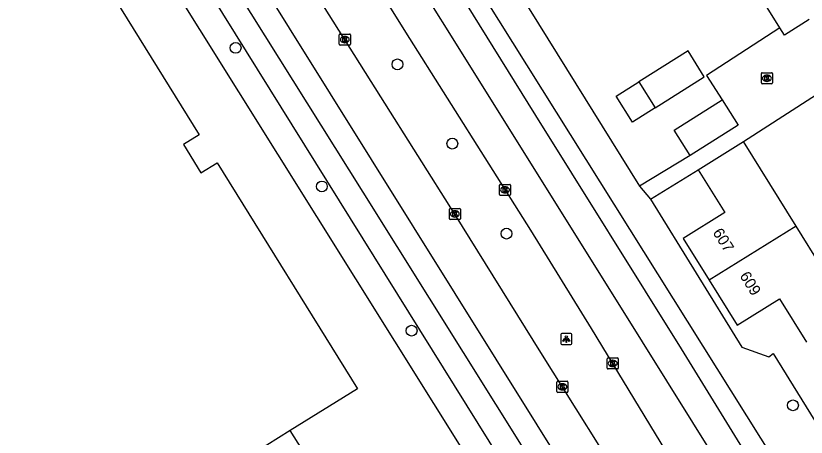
# Model space of a CAD drawing. Extents: x 158461 to 159795, y 387220 to 388672.
# Drawn here: x 158888.2 to 158959.6, y 387763.8 to 387801.9 of the extents above; entities that cross this region are included whole.
import ezdxf

# ---------------------------------------------------------------- set-up
doc = ezdxf.new("R2010")
doc.units = 0
for name, color, linetype in [('IMGEO_Boom', 7, 'Continuous'), ('IMGEO_Kolk', 7, 'Continuous'), ('IMGEO_Lichtpunt', 7, 'Continuous'), ('IMGEO_Pand', 7, 'Continuous'), ('IMGEO_Pand_nummerreeks', 7, 'Continuous'), ('IMGEO_Pand_overbouw', 7, 'Continuous'), ('IMGEO_Rijbaan_lokaal_gesloten', 7, 'Continuous'), ('IMGEO_Voetpad_open', 7, 'Continuous')]:
    doc.layers.add(name, color=color, linetype=linetype)

msp = doc.modelspace()

# ---------------------------------------------------------------- linework, layer by layer
at = {"layer": 'IMGEO_Boom'}
for centre in [(158908.058, 387799.024), (158922.686, 387797.535), (158927.646, 387790.371), (158915.855, 387786.504), (158932.542, 387782.242), (158923.969, 387773.474), (158958.436, 387766.729)]:
    msp.add_circle(centre, 0.489, dxfattribs=at)
at = {"layer": 'IMGEO_Kolk'}
for p, q in [((158917.426, 387799.346), (158917.426, 387800.198)), ((158917.501, 387800.272), (158918.353, 387800.272)), ((158918.427, 387800.198), (158918.427, 387799.346)), ((158917.937, 387799.492), (158917.912, 387799.492)), ((158917.914, 387800.052), (158917.939, 387800.052)), ((158918.353, 387799.272), (158917.501, 387799.272)), ((158955.584, 387795.853), (158955.584, 387796.705)), ((158955.659, 387796.779), (158956.511, 387796.779)), ((158956.072, 387796.559), (158956.097, 387796.559)), ((158956.585, 387796.705), (158956.585, 387795.853)), ((158956.095, 387795.999), (158956.07, 387795.999)), ((158956.511, 387795.779), (158955.659, 387795.779)), ((158931.91, 387785.767), (158931.91, 387786.619)), ((158931.985, 387786.693), (158932.837, 387786.693)), ((158932.911, 387786.619), (158932.911, 387785.767)), ((158932.421, 387785.913), (158932.396, 387785.913)), ((158932.398, 387786.473), (158932.423, 387786.473)), ((158932.837, 387785.693), (158931.985, 387785.693)), ((158927.376, 387783.592), (158927.376, 387784.444)), ((158927.451, 387784.518), (158928.303, 387784.518)), ((158928.377, 387784.444), (158928.377, 387783.592)), ((158927.887, 387783.738), (158927.862, 387783.738)), ((158927.864, 387784.298), (158927.889, 387784.298)), ((158928.303, 387783.518), (158927.451, 387783.518)), ((158941.646, 387770.092), (158941.646, 387770.944)), ((158941.721, 387771.018), (158942.573, 387771.018)), ((158942.134, 387770.798), (158942.159, 387770.798)), ((158942.647, 387770.944), (158942.647, 387770.092)), ((158942.157, 387770.238), (158942.132, 387770.238)), ((158942.573, 387770.018), (158941.721, 387770.018)), ((158937.095, 387767.975), (158937.095, 387768.827)), ((158937.17, 387768.901), (158938.022, 387768.901)), ((158937.583, 387768.681), (158937.608, 387768.681)), ((158938.096, 387768.827), (158938.096, 387767.975)), ((158937.606, 387768.121), (158937.581, 387768.121)), ((158938.022, 387767.901), (158937.17, 387767.901))]:
    msp.add_line(p, q, dxfattribs=at)
for points in [[(158917.426, 387799.346), (158917.426, 387800.198)], [(158917.501, 387800.272), (158918.353, 387800.272)], [(158918.427, 387800.198), (158918.427, 387799.346)], [(158917.747, 387799.972), (158917.87, 387799.972), (158917.87, 387799.821), (158918, 387799.972), (158918.164, 387799.972), (158918.018, 387799.821), (158918.171, 387799.572), (158918.019, 387799.572), (158917.934, 387799.736), (158917.87, 387799.669), (158917.87, 387799.572), (158917.747, 387799.572), (158917.747, 387799.972)], [(158918.353, 387799.272), (158917.501, 387799.272)], [(158955.584, 387795.853), (158955.584, 387796.705)], [(158955.659, 387796.779), (158956.511, 387796.779)], [(158956.585, 387796.705), (158956.585, 387795.853)], [(158955.905, 387796.479), (158956.028, 387796.479), (158956.028, 387796.328), (158956.158, 387796.479), (158956.322, 387796.479), (158956.176, 387796.328), (158956.329, 387796.079), (158956.177, 387796.079), (158956.092, 387796.243), (158956.028, 387796.176), (158956.028, 387796.079), (158955.905, 387796.079), (158955.905, 387796.479)], [(158956.511, 387795.779), (158955.659, 387795.779)], [(158931.91, 387785.767), (158931.91, 387786.619)], [(158931.985, 387786.693), (158932.837, 387786.693)], [(158932.911, 387786.619), (158932.911, 387785.767)], [(158932.231, 387786.393), (158932.354, 387786.393), (158932.354, 387786.242), (158932.484, 387786.393), (158932.648, 387786.393), (158932.502, 387786.242), (158932.655, 387785.993), (158932.503, 387785.993), (158932.418, 387786.157), (158932.354, 387786.09), (158932.354, 387785.993), (158932.231, 387785.993), (158932.231, 387786.393)], [(158932.837, 387785.693), (158931.985, 387785.693)], [(158927.376, 387783.592), (158927.376, 387784.444)], [(158927.451, 387784.518), (158928.303, 387784.518)], [(158928.377, 387784.444), (158928.377, 387783.592)], [(158927.697, 387784.218), (158927.82, 387784.218), (158927.82, 387784.067), (158927.95, 387784.218), (158928.114, 387784.218), (158927.968, 387784.067), (158928.121, 387783.818), (158927.969, 387783.818), (158927.884, 387783.982), (158927.82, 387783.915), (158927.82, 387783.818), (158927.697, 387783.818), (158927.697, 387784.218)], [(158928.303, 387783.518), (158927.451, 387783.518)], [(158941.646, 387770.092), (158941.646, 387770.944)], [(158941.721, 387771.018), (158942.573, 387771.018)], [(158942.647, 387770.944), (158942.647, 387770.092)], [(158941.967, 387770.718), (158942.09, 387770.718), (158942.09, 387770.567), (158942.22, 387770.718), (158942.384, 387770.718), (158942.238, 387770.567), (158942.391, 387770.318), (158942.239, 387770.318), (158942.154, 387770.482), (158942.09, 387770.415), (158942.09, 387770.318), (158941.967, 387770.318), (158941.967, 387770.718)], [(158942.573, 387770.018), (158941.721, 387770.018)], [(158937.095, 387767.975), (158937.095, 387768.827)], [(158937.17, 387768.901), (158938.022, 387768.901)], [(158938.096, 387768.827), (158938.096, 387767.975)], [(158937.416, 387768.601), (158937.539, 387768.601), (158937.539, 387768.45), (158937.669, 387768.601), (158937.833, 387768.601), (158937.687, 387768.45), (158937.84, 387768.201), (158937.688, 387768.201), (158937.603, 387768.365), (158937.539, 387768.298), (158937.539, 387768.201), (158937.416, 387768.201), (158937.416, 387768.601)], [(158938.022, 387767.901), (158937.17, 387767.901)]]:
    msp.add_lwpolyline(points, dxfattribs=at)
for centre, start, end in [((158917.503, 387800.196), 91.55205, 178.44795), ((158917.503, 387800.196), 91.55205, 178.44795), ((158918.351, 387800.196), 1.55205, 88.44795), ((158918.351, 387800.196), 1.55205, 88.44795), ((158917.503, 387799.348), 181.55205, 268.44795), ((158917.503, 387799.348), 181.55205, 268.44795), ((158918.351, 387799.348), 271.55205, 358.44795), ((158918.351, 387799.348), 271.55205, 358.44795), ((158955.661, 387796.703), 91.55205, 178.44795), ((158955.661, 387796.703), 91.55205, 178.44795), ((158956.509, 387796.703), 1.55205, 88.44795), ((158956.509, 387796.703), 1.55205, 88.44795), ((158955.661, 387795.855), 181.55205, 268.44795), ((158955.661, 387795.855), 181.55205, 268.44795), ((158956.509, 387795.855), 271.55205, 358.44795), ((158956.509, 387795.855), 271.55205, 358.44795), ((158931.987, 387786.617), 91.55205, 178.44795), ((158931.987, 387786.617), 91.55205, 178.44795), ((158932.835, 387786.617), 1.55205, 88.44795), ((158932.835, 387786.617), 1.55205, 88.44795), ((158931.987, 387785.769), 181.55205, 268.44795), ((158931.987, 387785.769), 181.55205, 268.44795), ((158932.835, 387785.769), 271.55205, 358.44795), ((158932.835, 387785.769), 271.55205, 358.44795), ((158927.453, 387784.442), 91.55205, 178.44795), ((158927.453, 387784.442), 91.55205, 178.44795), ((158928.301, 387784.442), 1.55205, 88.44795), ((158928.301, 387784.442), 1.55205, 88.44795), ((158927.453, 387783.594), 181.55205, 268.44795), ((158927.453, 387783.594), 181.55205, 268.44795), ((158928.301, 387783.594), 271.55205, 358.44795), ((158928.301, 387783.594), 271.55205, 358.44795), ((158941.723, 387770.942), 91.55205, 178.44795), ((158941.723, 387770.942), 91.55205, 178.44795), ((158942.571, 387770.942), 1.55205, 88.44795), ((158942.571, 387770.942), 1.55205, 88.44795), ((158941.723, 387770.094), 181.55205, 268.44795), ((158941.723, 387770.094), 181.55205, 268.44795), ((158942.571, 387770.094), 271.55205, 358.44795), ((158942.571, 387770.094), 271.55205, 358.44795), ((158937.172, 387768.825), 91.55205, 178.44795), ((158937.172, 387768.825), 91.55205, 178.44795), ((158938.02, 387768.825), 1.55205, 88.44795), ((158938.02, 387768.825), 1.55205, 88.44795), ((158937.172, 387767.977), 181.55205, 268.44795), ((158937.172, 387767.977), 181.55205, 268.44795), ((158938.02, 387767.977), 271.55205, 358.44795), ((158938.02, 387767.977), 271.55205, 358.44795)]:
    msp.add_arc(centre, 0.0765, start, end, dxfattribs=at)
for centre, major_axis, ratio, start_param, end_param in [((158917.913, 387799.772), (-0.387, 0.002), 0.722429, 4.712389, 7.853982), ((158917.938, 387799.772), (-0.39, 0.002), 0.717154, 1.570796, 4.712389), ((158956.071, 387796.279), (-0.387, 0.002), 0.722429, 4.712389, 7.853982), ((158956.096, 387796.279), (-0.39, 0.002), 0.717154, 1.570796, 4.712389), ((158932.397, 387786.193), (-0.387, 0.002), 0.722429, 4.712389, 7.853982), ((158932.422, 387786.193), (-0.39, 0.002), 0.717154, 1.570796, 4.712389), ((158927.863, 387784.018), (-0.387, 0.002), 0.722429, 4.712389, 7.853982), ((158927.888, 387784.018), (-0.39, 0.002), 0.717154, 1.570796, 4.712389), ((158942.133, 387770.518), (-0.387, 0.002), 0.722429, 4.712389, 7.853982), ((158942.158, 387770.518), (-0.39, 0.002), 0.717154, 1.570796, 4.712389), ((158937.582, 387768.401), (-0.387, 0.002), 0.722429, 4.712389, 7.853982), ((158937.607, 387768.401), (-0.39, 0.002), 0.717154, 1.570796, 4.712389)]:
    msp.add_ellipse(centre, major_axis=major_axis, ratio=ratio, start_param=start_param, end_param=end_param, dxfattribs=at)
at = {"layer": 'IMGEO_Lichtpunt'}
for p, q in [((158937.448, 387773.119), (158937.448, 387772.312)), ((158937.448, 387773.119), (158937.448, 387772.312)), ((158938.35, 387773.214), (158937.542, 387773.214)), ((158938.35, 387773.214), (158937.542, 387773.214)), ((158938.444, 387772.312), (158938.444, 387773.119)), ((158938.444, 387772.312), (158938.444, 387773.119)), ((158937.542, 387772.218), (158938.35, 387772.218)), ((158937.542, 387772.218), (158938.35, 387772.218))]:
    msp.add_line(p, q, dxfattribs=at)
for points in [[(158937.822, 387772.783), (158937.861, 387772.755), (158937.673, 387772.493), (158937.635, 387772.52), (158937.822, 387772.783)], [(158937.924, 387772.735), (158937.971, 387772.735), (158937.971, 387772.413), (158937.924, 387772.413), (158937.924, 387772.735)], [(158938.034, 387772.755), (158938.072, 387772.782), (158938.259, 387772.52), (158938.22, 387772.492), (158938.034, 387772.755)]]:
    msp.add_lwpolyline(points, dxfattribs=at)
msp.add_circle((158937.947, 387772.917), 0.0994, dxfattribs=at)
for centre, start, end in [((158937.542, 387773.119), 90, 180), ((158937.542, 387773.119), 90, 180), ((158938.35, 387773.119), 0, 90), ((158938.35, 387773.119), 0, 90), ((158937.542, 387772.312), 180, 270), ((158937.542, 387772.312), 180, 270), ((158938.35, 387772.312), 270, 0), ((158938.35, 387772.312), 270, 360)]:
    msp.add_arc(centre, 0.0946, start, end, dxfattribs=at)
at = {"layer": 'IMGEO_Pand'}
for points in [[(158843.421, 387765.958), (158844.968, 387766.918), (158843.413, 387769.421), (158841.881, 387768.47), (158822.272, 387800.049), (158819.635, 387804.296), (158853.129, 387825.094), (158836.694, 387851.56), (158837.362, 387851.975), (158838.447, 387850.227), (158852.702, 387859.079), (158851.58, 387860.885), (158852.446, 387861.423), (158876.367, 387822.901), (158879.485, 387824.836), (158881.375, 387821.792), (158884.521, 387823.745), (158904.752, 387791.165), (158903.336, 387790.286), (158904.922, 387787.732), (158906.392, 387788.644), (158919.073, 387768.222), (158912.998, 387764.449), (158909.819, 387762.475)], [(158957.256, 387800.841), (158954.953, 387804.527), (158957.154, 387805.902)], [(158959.907, 387801.574), (158957.671, 387800.177), (158957.256, 387800.841)], [(158945.983, 387793.613), (158950.421, 387796.406), (158948.951, 387798.743), (158944.513, 387795.95)], [(158945.983, 387793.613), (158943.939, 387792.327), (158942.468, 387794.664), (158944.513, 387795.95)], [(158944.513, 387795.95), (158945.983, 387793.613)], [(158949.147, 387789.296), (158947.701, 387791.584), (158952.042, 387794.328)], [(158952.042, 387794.328), (158953.488, 387792.04), (158949.147, 387789.296)], [(158949.861, 387788.002), (158953.966, 387790.556)], [(158958.722, 387782.915), (158953.966, 387790.556)], [(158949.861, 387788.002), (158952.266, 387784.138), (158948.514, 387781.803), (158950.865, 387778.025)], [(158958.722, 387782.915), (158950.865, 387778.025)], [(158961.052, 387779.171), (158958.722, 387782.915)], [(158950.865, 387778.025), (158953.387, 387773.973), (158957.226, 387776.362), (158959.674, 387772.428)]]:
    msp.add_lwpolyline(points, dxfattribs=at)
at = {"layer": 'IMGEO_Pand_overbouw'}
msp.add_lwpolyline([(158912.998, 387764.449), (158909.819, 387762.475), (158915.409, 387753.472), (158914.831, 387751.001), (158915.852, 387750.762), (158915.674, 387750), (158914.676, 387745.736), (158913.693, 387745.966), (158913.104, 387743.448), (158904.11, 387737.863), (158906.073, 387734.701), (158908.633, 387736.316), (158912.731, 387729.822), (158918.568, 387755.623)], close=True, dxfattribs=at)
at = {"layer": 'IMGEO_Rijbaan_lokaal_gesloten'}
for points in [[(158887.922, 387863.502), (158910.852, 387826.792), (158942.469, 387776.24), (158958.617, 387750.353), (158960.418, 387747.762), (158961.612, 387746.321), (158963.393, 387744.535), (158965.421, 387742.895), (158967.458, 387741.572), (158969.689, 387740.407), (158971.94, 387739.465), (158974.416, 387738.664), (158976.417, 387738.226), (158979.369, 387737.931), (158981.889, 387737.858), (159007.45, 387739.32), (159019.867, 387740.171), (159032.856, 387742.163)], [(158877.701, 387857.148), (158898.064, 387824.564), (158950.111, 387741.221), (158948.001, 387740.023)], [(158875.717, 387855.924), (158883.633, 387843.333), (158898.324, 387819.878), (158900.577, 387816.28), (158919.568, 387785.998), (158934.623, 387761.938), (158942.187, 387750), (158945.11, 387745.294), (158947.991, 387740.043)], [(158894.338, 387846.957), (158900.756, 387836.663), (158907.93, 387825.243), (158911.116, 387820.171), (158923.424, 387800.449), (158934.705, 387782.558), (158940.201, 387773.668), (158950.329, 387757.013)], [(158946.243, 387754.475), (158944.106, 387758.001), (158935.66, 387771.491), (158927.886, 387784.002), (158921.172, 387794.614), (158912.191, 387808.884), (158905.426, 387819.705), (158903.516, 387822.778), (158895.047, 387836.397), (158890.044, 387844.243)], [(158959.591, 387753.588), (158948.358, 387771.822), (158935.188, 387792.904), (158922.531, 387813.295), (158913.231, 387828.204), (158908.724, 387835.428), (158907.553, 387837.293)]]:
    msp.add_lwpolyline(points, dxfattribs=at)
at = {"layer": 'IMGEO_Voetpad_open'}
for points in [[(158946.265, 387734.359), (158945.05, 387736.345), (158936.552, 387750), (158894.251, 387817.603), (158856.23, 387878.364)], [(158873.919, 387855.065), (158896.474, 387818.845), (158939.346, 387750), (158944.861, 387741.144)], [(158959.476, 387757.471), (158914.647, 387828.995), (158910.604, 387835.446)], [(158927.158, 387814.532), (158944.563, 387786.519)], [(158957.256, 387800.841), (158950.62, 387796.539), (158952.042, 387794.328)], [(158953.966, 387790.556), (158967.683, 387799.376), (158971.991, 387798.773), (158972.626, 387797.91)], [(158949.147, 387789.296), (158944.563, 387786.519)], [(158945.564, 387785.349), (158949.861, 387788.002)], [(158944.563, 387786.519), (158945.564, 387785.349)], [(158945.564, 387785.349), (158953.827, 387771.988), (158956.246, 387771.106), (158956.636, 387771.426), (158961.841, 387763.046), (158961.521, 387762.826), (158961.041, 387760.377), (158965.166, 387753.767), (158968.506, 387750), (158969.131, 387749.295)]]:
    msp.add_lwpolyline(points, dxfattribs=at)

# ---------------------------------------------------------------- texts
at = {"layer": 'IMGEO_Pand_nummerreeks'}
for s, p in [('607', (158951.143, 387782.347)), ('609', (158953.58, 387778.432))]:
    msp.add_text(s, height=1, rotation=301.89607, dxfattribs=at).set_placement(p)

doc.saveas('drawing.dxf')
